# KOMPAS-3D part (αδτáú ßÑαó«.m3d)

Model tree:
1. Эскиз:1
2. Операция выдавливания:1
     Расстояние 1 = 1.5; Расстояние 2 = 7.2
3. Эскиз:4
4. Вырезать элемент выдавливания:2
     Расстояние 1 = 3
5. Эскиз:5
6. Операция выдавливания:3
     Расстояние 1 = 3; Расстояние 2 = 7.2

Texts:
  stalker61
  Сплав АЛ8  ГОСТ 1583-93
